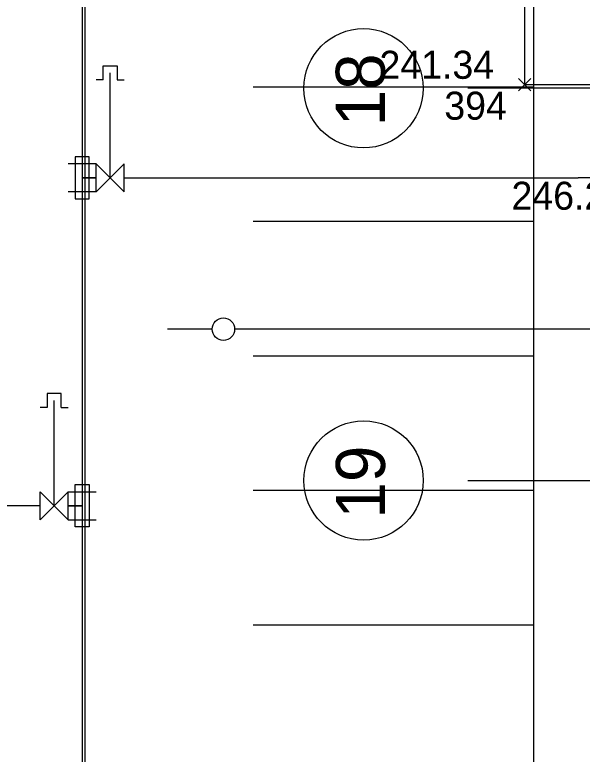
# Model space of a CAD drawing. Extents: x -264205 to -263659, y -1242401 to -1242060.
# Drawn here: x -263925.35 to -263915.22, y -1242207.77 to -1242194.57 of the extents above; entities that cross this region are included whole.
import ezdxf

# ---------------------------------------------------------------- set-up
doc = ezdxf.new("R2010")
doc.units = 0
for name, color, linetype in [('BOD_CISLO', 7, 'Continuous'), ('BOD_SYMBOL', 7, 'Continuous'), ('BOD_VYSKA', 7, 'Continuous'), ('KFA_SO_10-1_TRIBUNA_A_HLAVNA_BUDOVA', 7, 'Continuous'), ('OSI_STAVBY_KFA', 7, 'Continuous'), ('SITUACIA_DSP_2D', 7, 'Continuous'), ('TDZ_VODOROVNE_PROJEKT', 7, 'Continuous')]:
    doc.layers.add(name, color=color, linetype=linetype)

msp = doc.modelspace()

# ---------------------------------------------------------------- linework, layer by layer
at = {"layer": 'BOD_SYMBOL'}
for p, q in [((-263916.361, -1242195.927), (-263916.139, -1242195.705)), ((-263916.139, -1242195.927), (-263916.361, -1242195.705))]:
    msp.add_line(p, q, dxfattribs=at)
at = {"layer": 'KFA_SO_10-1_TRIBUNA_A_HLAVNA_BUDOVA'}
for p, q in [((-263916.245, -1242132.722), (-263916.25, -1242195.816)), ((-263916.25, -1242195.816), (-263914.23, -1242195.816))]:
    msp.add_line(p, q, dxfattribs=at)
at = {"layer": 'OSI_STAVBY_KFA'}
for p, q in [((-263792.653, -1242195.882), (-263917.263, -1242195.882)), ((-263917.265, -1242202.882), (-263905.505, -1242202.882)), ((-263917.265, -1242202.882), (-263905.505, -1242202.882))]:
    msp.add_line(p, q, dxfattribs=at)
for centre in [(-263919.125, -1242195.882), (-263919.123, -1242202.882)]:
    msp.add_circle(centre, 1.064, dxfattribs=at)
at = {"layer": 'SITUACIA_DSP_2D'}
for p, q in [((-263924.143, -1242185.14), (-263924.143, -1242250.14)), ((-263923.768, -1242195.732), (-263923.768, -1242195.482)), ((-263923.768, -1242195.482), (-263923.518, -1242195.482)), ((-263923.518, -1242195.482), (-263923.518, -1242195.732)), ((-263923.643, -1242197.482), (-263923.643, -1242195.607)), ((-263923.768, -1242195.732), (-263923.893, -1242195.732)), ((-263923.518, -1242195.732), (-263923.393, -1242195.732)), ((-263924.018, -1242197.107), (-263924.268, -1242197.107)), ((-263924.268, -1242197.107), (-263924.268, -1242197.857)), ((-263924.018, -1242197.857), (-263924.018, -1242197.107)), ((-263923.893, -1242197.232), (-263924.393, -1242197.232)), ((-263923.893, -1242197.732), (-263923.893, -1242197.232)), ((-263923.893, -1242197.232), (-263923.393, -1242197.732)), ((-263923.393, -1242197.232), (-263923.893, -1242197.732)), ((-263923.393, -1242197.732), (-263923.393, -1242197.232)), ((-263924.143, -1242197.482), (-263923.893, -1242197.482)), ((-263923.893, -1242197.482), (-263924.143, -1242197.482)), ((-263923.393, -1242197.482), (-263915.293, -1242197.482)), ((-263914.293, -1242197.482), (-263915.293, -1242197.482)), ((-263923.893, -1242197.732), (-263924.393, -1242197.732)), ((-263924.268, -1242197.857), (-263924.018, -1242197.857)), ((-263921.824, -1242200.182), (-263922.624, -1242200.182)), ((-263915.293, -1242200.182), (-263921.424, -1242200.182)), ((-263909.043, -1242200.182), (-263915.293, -1242200.182)), ((-263924.768, -1242201.332), (-263924.768, -1242201.582)), ((-263924.518, -1242201.332), (-263924.768, -1242201.332)), ((-263924.518, -1242201.582), (-263924.518, -1242201.332)), ((-263924.643, -1242203.332), (-263924.643, -1242201.457)), ((-263924.768, -1242201.582), (-263924.893, -1242201.582)), ((-263924.518, -1242201.582), (-263924.393, -1242201.582)), ((-263924.268, -1242203.707), (-263924.268, -1242202.957)), ((-263924.268, -1242202.957), (-263924.018, -1242202.957)), ((-263924.018, -1242202.957), (-263924.018, -1242203.707)), ((-263924.893, -1242203.582), (-263924.893, -1242203.082)), ((-263924.393, -1242203.082), (-263924.893, -1242203.582)), ((-263924.893, -1242203.082), (-263924.393, -1242203.582)), ((-263924.393, -1242203.582), (-263924.393, -1242203.082)), ((-263924.393, -1242203.082), (-263923.893, -1242203.082)), ((-263924.893, -1242203.332), (-263958.097, -1242203.332)), ((-263924.143, -1242203.332), (-263924.393, -1242203.332)), ((-263924.393, -1242203.332), (-263924.143, -1242203.332)), ((-263924.393, -1242203.582), (-263923.893, -1242203.582)), ((-263924.018, -1242203.707), (-263924.268, -1242203.707))]:
    msp.add_line(p, q, dxfattribs=at)
msp.add_circle((-263921.624, -1242200.182), 0.2, dxfattribs=at)
at = {"layer": 'TDZ_VODOROVNE_PROJEKT'}
for p, q in [((-263924.088, -1242241.458), (-263924.093, -1242087.307)), ((-263916.093, -1242187.557), (-263916.093, -1242241.458)), ((-263921.093, -1242195.857), (-263916.093, -1242195.857)), ((-263921.093, -1242198.257), (-263916.093, -1242198.257)), ((-263921.093, -1242200.657), (-263916.093, -1242200.657)), ((-263921.093, -1242203.057), (-263916.093, -1242203.057)), ((-263921.093, -1242205.457), (-263916.093, -1242205.457))]:
    msp.add_line(p, q, dxfattribs=at)

# ---------------------------------------------------------------- texts
at = {"layer": 'BOD_CISLO'}
msp.add_text('394', height=0.5, dxfattribs=at).set_placement((-263917.683, -1242196.443))
at = {"layer": 'BOD_VYSKA'}
for s, p in [('241.34', (-263918.84, -1242195.713)), ('246.26', (-263916.485, -1242198.05))]:
    msp.add_text(s, height=0.5, dxfattribs=at).set_placement(p)
at = {"layer": 'OSI_STAVBY_KFA'}
for s, p in [('18', (-263918.744, -1242196.562)), ('19', (-263918.742, -1242203.562))]:
    msp.add_text(s, height=0.875, rotation=90, dxfattribs=at).set_placement(p)

doc.saveas('drawing.dxf')
